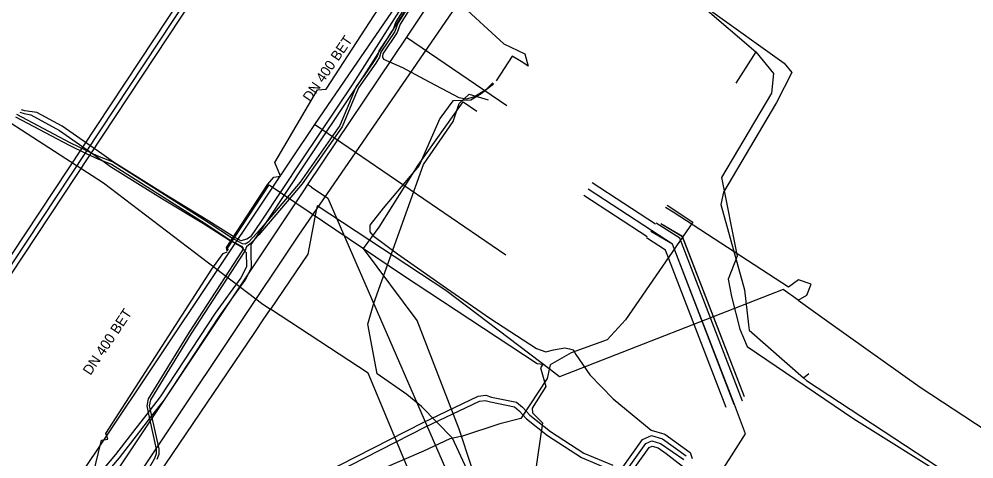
# Model space of a CAD drawing. Extents: x -598233 to -596890, y -1157848 to -1156431.
# Drawn here: x -597025.8 to -596950, y -1157211.3 to -1157176.4 of the extents above; entities that cross this region are included whole.
import ezdxf

# ---------------------------------------------------------------- set-up
doc = ezdxf.new("R2010")
doc.units = 0
for name, color, linetype in [('Vrstva 12', 7, 'Continuous'), ('Vrstva 13', 7, 'Continuous'), ('Vrstva 16', 7, 'Continuous'), ('Vrstva 19', 7, 'Continuous'), ('Vrstva 25', 7, 'Continuous'), ('Vrstva 26', 7, 'Continuous'), ('Vrstva 37', 7, 'Continuous'), ('Vrstva 38', 7, 'Continuous'), ('Vrstva 42', 7, 'Continuous'), ('Vrstva 55', 7, 'Continuous'), ('Vrstva 58', 7, 'Continuous'), ('Vrstva 9', 7, 'Continuous')]:
    doc.layers.add(name, color=color, linetype=linetype)

msp = doc.modelspace()

# ---------------------------------------------------------------- linework, layer by layer
at = {"layer": 'Vrstva 12'}
for points in [[(-597032.93, -1157180.49), (-597019.07, -1157189.44), (-597010.72, -1157195.79), (-597006.41, -1157199.06)], [(-596991.89, -1157197.98), (-597002.1, -1157191.27), (-597002.27, -1157192.15), (-597002.84, -1157195.09), (-597005.8, -1157199.46)], [(-596974.32, -1157191.21), (-596972.26, -1157192.55), (-596977.62, -1157200.29), (-596979.08, -1157201.89), (-596981.93, -1157202.92), (-596983.59, -1157203.86), (-596983.83, -1157204.96), (-596985.93, -1157208.12), (-596987.59, -1157208.54), (-596990.56, -1157209.52), (-596991.56, -1157209.75), (-596993.66, -1157210.73), (-596996.91, -1157212.12), (-596995.88, -1157213.75), (-596995.41, -1157214.6), (-596992.85, -1157218.63), (-596989.76, -1157224.28), (-596987.91, -1157228.68), (-596983.13, -1157231.73), (-596982.3, -1157232.26), (-596981.48, -1157232.92)], [(-596973.84, -1157191.76), (-596974.43, -1157191.38)], [(-596963.91, -1157198.75), (-596963.22, -1157198.34), (-596962.89, -1157197.48), (-596963.87, -1157197.14), (-596964.68, -1157197.72), (-596973.84, -1157191.76)], [(-596983.58, -1157204.27), (-596991.89, -1157197.98)], [(-596965.1, -1157197.9), (-596982.85, -1157204.83), (-596983.58, -1157204.27)], [(-596963.91, -1157198.75), (-596965.1, -1157197.9)], [(-596963.91, -1157198.75), (-596961.48, -1157200.48), (-596954.23, -1157205.63), (-596922.86, -1157226.22), (-596910.53, -1157233.01), (-596897.62, -1157241.15), (-596890.462, -1157245.858)], [(-597006.41, -1157199.06), (-597005.8, -1157199.46)], [(-597006.32, -1157200.23), (-597005.8, -1157199.46)], [(-596986.93, -1157231.06), (-596989.34, -1157225.4), (-596998.05, -1157204.54), (-597005.8, -1157199.46)], [(-597007.05, -1157201.3), (-597006.32, -1157200.23)], [(-597014.81, -1157212.79), (-597014.11, -1157211.71), (-597007.05, -1157201.3)]]:
    msp.add_lwpolyline(points, dxfattribs=at)
at = {"layer": 'Vrstva 13'}
for p, q in [((-596995.007, -1157177.869), (-596987.029, -1157183.302)), ((-597002.856, -1157189.564), (-597003.086, -1157189.907)), ((-597002.549, -1157189.771), (-597002.856, -1157189.564))]:
    msp.add_line(p, q, dxfattribs=at)
for points in [[(-596966.104, -1157134.786), (-596979.775, -1157155.164), (-596980.79, -1157156.59), (-596995.007, -1157177.869), (-597002.856, -1157189.564)], [(-597003.086, -1157189.907), (-597026.958, -1157225.685), (-597068.888, -1157237.453)], [(-597002.549, -1157189.771), (-597001.246, -1157190.659), (-596990.925, -1157214.348), (-596989.181, -1157218.344), (-596977.644, -1157244.817), (-596976.574, -1157247.274), (-596974.945, -1157251.212), (-596963.817, -1157276.638), (-596961.383, -1157282.176), (-596957.612, -1157290.782), (-596980.006, -1157323.339), (-596973.121, -1157340.272), (-596970.958, -1157345.591), (-596971.266, -1157347.162)]]:
    msp.add_lwpolyline(points, dxfattribs=at)
at = {"layer": 'Vrstva 16'}
for points in [[(-596998.41, -1157194.64), (-596997.18, -1157192.95), (-596994.09, -1157188.03), (-596990.51, -1157183.01), (-596989.41, -1157183.76)], [(-596961.79, -1157277.86), (-596964.67, -1157268.74), (-596973.69, -1157248.35), (-596975.09, -1157245.91), (-596978.64, -1157237.11), (-596983.01, -1157226.86), (-596984.86, -1157222.75), (-596987.47, -1157216.28), (-596989.85, -1157211.94), (-596990.83, -1157208.98), (-596994.15, -1157200.36), (-596998.41, -1157194.64)]]:
    msp.add_lwpolyline(points, dxfattribs=at)
at = {"layer": 'Vrstva 19'}
for points in [[(-596972.6, -1157147.95), (-596981.12, -1157160.92), (-597002.182, -1157191.556)], [(-597002.182, -1157191.556), (-597003.58, -1157193.59), (-597033.4, -1157238.15), (-597034.34, -1157239.12), (-597026.35, -1157257.65), (-597011.73, -1157291.16), (-597000.9, -1157316.42), (-597000.59, -1157317.13)]]:
    msp.add_lwpolyline(points, dxfattribs=at)
at = {"layer": 'Vrstva 25'}
msp.add_line((-597009.314, -1157170.114), (-597030.436, -1157202.016), dxfattribs=at)
at = {"layer": 'Vrstva 26'}
for p, q in [((-597030.551, -1157201.465), (-597009.427, -1157169.56)), ((-597009.202, -1157170.669), (-597030.103, -1157202.237))]:
    msp.add_line(p, q, dxfattribs=at)
at = {"layer": 'Vrstva 37'}
msp.add_line((-596975.561, -1157193.208), (-596980.59, -1157189.936), dxfattribs=at)
for points in [[(-596968.182, -1157206.411), (-596973.091, -1157193.703), (-596974.818, -1157192.69)], [(-596968.975, -1157207.006), (-596973.884, -1157194.298), (-596975.611, -1157193.285)], [(-596968.975, -1157207.006), (-596973.884, -1157194.298), (-596975.561, -1157193.208)], [(-596962.011, -1157224.901), (-596964.78, -1157223.133), (-596973.39, -1157217.635), (-596968.09, -1157209.335), (-596968.975, -1157207.006)]]:
    msp.add_lwpolyline(points, dxfattribs=at)
at = {"layer": 'Vrstva 38'}
for p, q in [((-596975.234, -1157192.705), (-596980.263, -1157189.433)), ((-596975.888, -1157193.711), (-596980.917, -1157190.439))]:
    msp.add_line(p, q, dxfattribs=at)
for points in [[(-596968.322, -1157206.754), (-596973.313, -1157193.835), (-596975.18, -1157192.621)], [(-596969.628, -1157207.258), (-596974.455, -1157194.761), (-596975.942, -1157193.795)]]:
    msp.add_lwpolyline(points, dxfattribs=at)
at = {"layer": 'Vrstva 42'}
for points in [[(-596993.928, -1157173.602), (-596995.861, -1157176.672), (-596996.094, -1157177.324), (-596996.1, -1157177.339), (-596996.164, -1157177.434), (-596997.205, -1157178.968), (-596997.265, -1157179.166), (-596997.319, -1157179.343), (-596997.614, -1157179.825), (-596998.375, -1157180.912), (-596998.998, -1157181.801), (-596999.097, -1157182.035), (-596999.532, -1157183.061), (-597000.298, -1157184.881), (-597003.449, -1157189.379), (-597006.068, -1157192.478), (-597006.874, -1157193.433), (-597007.561, -1157194.13), (-597007.803, -1157194.293), (-597008.013, -1157194.282), (-597008.909, -1157193.804), (-597010.665, -1157192.626), (-597018.335, -1157187.78), (-597019.381, -1157187.378), (-597019.912, -1157187.129), (-597020.337, -1157186.93), (-597021.695, -1157186.271), (-597025.953, -1157184.012)], [(-596993.76, -1157173.71), (-596995.68, -1157176.76), (-596995.92, -1157177.43), (-596997.04, -1157179.08), (-596997.151, -1157179.452), (-596997.446, -1157179.935), (-596998.822, -1157181.899), (-596999.348, -1157183.139), (-597000.122, -1157184.979), (-597003.291, -1157189.501), (-597006.726, -1157193.567), (-597007.028, -1157193.874), (-597007.419, -1157194.27), (-597007.706, -1157194.498), (-597007.844, -1157194.843), (-597007.856, -1157194.875), (-597012.096, -1157201.394), (-597015.335, -1157206.637), (-597015.428, -1157207.119), (-597015.356, -1157207.444), (-597015.243, -1157207.953), (-597014.67, -1157210.54), (-597014.68, -1157210.969), (-597014.829, -1157211.382)], [(-596994.499, -1157174.068), (-596999.276, -1157181.586), (-597003.32, -1157187.612), (-597006.546, -1157192.475), (-597007.402, -1157193.712), (-597007.689, -1157193.913), (-597008.155, -1157194.028), (-597008.849, -1157193.644), (-597010.921, -1157192.331), (-597014.153, -1157190.369), (-597018.269, -1157187.806), (-597019.202, -1157187.137), (-597022.349, -1157184.938), (-597024.347, -1157183.844), (-597025.293, -1157183.734), (-597025.582, -1157183.653)], [(-597019.913, -1157213.742), (-597017.796, -1157211.239), (-597016.165, -1157209.149), (-597015.402, -1157208.159), (-597015.243, -1157207.953), (-597014.227, -1157206.634), (-597009.862, -1157200.009), (-597007.803, -1157197.166), (-597007.298, -1157196.174), (-597007.339, -1157195.016), (-597007.349, -1157194.337), (-597007.028, -1157193.874), (-597006.214, -1157192.699), (-597006.068, -1157192.478), (-597002.988, -1157187.834), (-596999.097, -1157182.035), (-596998.942, -1157181.804), (-596998.375, -1157180.912), (-596997.265, -1157179.166), (-596996.164, -1157177.434), (-596996.094, -1157177.324), (-596994.161, -1157174.282)], [(-596993.592, -1157173.818), (-596995.499, -1157176.848), (-596995.74, -1157177.521), (-596996.875, -1157179.192), (-596996.897, -1157179.43), (-596996.82, -1157179.62), (-596995.33, -1157180.29), (-596993.59, -1157181.21), (-596990.85, -1157182.66), (-596990.24, -1157182.78), (-596989.66, -1157182.6), (-596988.66, -1157181.99), (-596988.15, -1157181.51)], [(-596990.792, -1157175.174), (-596987.283, -1157178.411), (-596985.616, -1157179.202), (-596985.335, -1157180.175), (-596985.767, -1157179.887), (-596986.026, -1157179.728), (-596986.608, -1157179.394), (-596987.895, -1157181.352)], [(-596988.093, -1157181.556), (-596988.216, -1157181.685), (-596989.073, -1157182.371), (-596989.898, -1157182.888), (-596991.326, -1157182.916), (-596992.371, -1157184.336), (-596993.997, -1157188.047), (-596996.87, -1157191.435), (-596997.904, -1157192.786), (-596997.927, -1157193.311), (-596997.685, -1157193.609), (-596995.722, -1157195.074), (-596991.832, -1157197.791), (-596988.383, -1157200.165), (-596984.689, -1157202.57), (-596983.938, -1157202.849), (-596983.329, -1157202.668), (-596982.443, -1157202.529), (-596982.075, -1157202.608), (-596981.766, -1157202.692), (-596981.572, -1157203.06), (-596980.445, -1157204.655), (-596978.601, -1157206.564), (-596975.591, -1157209.04), (-596974.492, -1157209.375), (-596972.484, -1157210.831), (-596972.314, -1157211.31)], [(-597026.047, -1157184.188), (-597021.785, -1157186.449), (-597020.423, -1157187.11), (-597019.459, -1157187.562), (-597019.105, -1157187.698), (-597018.425, -1157187.96), (-597010.775, -1157192.794), (-597009.011, -1157193.976), (-597008.107, -1157194.458), (-597008.004, -1157194.581), (-597008.011, -1157194.65), (-597008.024, -1157194.765), (-597012.264, -1157201.286), (-597015.525, -1157206.563), (-597015.632, -1157207.121), (-597015.515, -1157207.65), (-597015.402, -1157208.159), (-597014.87, -1157210.56), (-597014.88, -1157210.931), (-597015.011, -1157211.298), (-597015.516, -1157212.179)], [(-597025.698, -1157183.828), (-597025.347, -1157183.926), (-597024.836, -1157184.032), (-597022.561, -1157185.278), (-597019.912, -1157187.129), (-597019.434, -1157187.463), (-597019.105, -1157187.698), (-597018.491, -1157188.138), (-597014.363, -1157190.709), (-597011.131, -1157192.671), (-597009.053, -1157193.988), (-597008.153, -1157194.487), (-597008.011, -1157194.65), (-597007.844, -1157194.843), (-597007.742, -1157194.96), (-597007.702, -1157196.084), (-597008.145, -1157196.956), (-597010.192, -1157199.781), (-597014.553, -1157206.402), (-597015.356, -1157207.444), (-597015.515, -1157207.65), (-597016.481, -1157208.903), (-597018.106, -1157210.987), (-597020.221, -1157213.488)], [(-596968.18, -1157206.41), (-596973.09, -1157193.7), (-596974.82, -1157192.69)], [(-596968.98, -1157207.01), (-596973.88, -1157194.3), (-596975.61, -1157193.28)], [(-597005.552, -1157214.492), (-596993.683, -1157208.432), (-596989.314, -1157206.358), (-596988.713, -1157206.288), (-596988.244, -1157206.425), (-596986.26, -1157206.841), (-596985.787, -1157207.228), (-596985.215, -1157207.853), (-596983.57, -1157209.155), (-596980.928, -1157210.874), (-596978.625, -1157211.84)], [(-597005.364, -1157214.845), (-596993.506, -1157208.791), (-596989.202, -1157206.748), (-596988.747, -1157206.695), (-596988.341, -1157206.813), (-596986.438, -1157207.212), (-596986.063, -1157207.519), (-596985.488, -1157208.147), (-596983.804, -1157209.48), (-596981.116, -1157211.229), (-596978.797, -1157212.201)], [(-596977.97, -1157212.183), (-596976.265, -1157209.781), (-596975.564, -1157209.466), (-596974.673, -1157209.738), (-596972.801, -1157211.096)], [(-596977.711, -1157212.516), (-596976.002, -1157210.101), (-596975.537, -1157209.892), (-596974.849, -1157210.102), (-596972.992, -1157211.387)], [(-596977.003, -1157212.208), (-596975.738, -1157210.421), (-596975.509, -1157210.319), (-596975.025, -1157210.466), (-596974.38, -1157210.913), (-596972.38, -1157212.475)]]:
    msp.add_lwpolyline(points, dxfattribs=at)
at = {"layer": 'Vrstva 55'}
for points in [[(-597009.195, -1157194.841), (-597009.25, -1157194.82), (-597009.282, -1157194.558), (-597006.002, -1157189.543), (-597005.55, -1157188.98), (-597005.02, -1157188.91), (-597005.46, -1157187.82), (-597002.06, -1157182.05), (-597001.39, -1157182), (-596995.49, -1157172.9)], [(-597009.156, -1157194.776), (-597009.178, -1157194.582), (-597005.919, -1157189.598), (-596995.32, -1157196.73), (-596984.621, -1157203.752), (-596984.18, -1157203.82), (-596984.353, -1157204.097), (-596983.94, -1157205.59), (-596985.03, -1157207.3), (-596984.99, -1157207.69), (-596984.2, -1157208.46), (-596984.99, -1157213.92)], [(-597030.878, -1157239.493), (-597023.909, -1157236.564), (-597021.97, -1157235.8), (-597021.7, -1157235.49), (-597023.94, -1157229.29), (-597024.33, -1157229.14), (-597024.03, -1157228.89), (-597023.6, -1157226.75), (-597020.69, -1157221.03), (-597018.98, -1157218.19), (-597019.33, -1157217.4), (-597019.91, -1157212.67), (-597019.23, -1157209.85), (-597018.72, -1157209.76), (-597018.88, -1157209.32), (-597010.47, -1157196.29), (-597009.55, -1157195.05), (-597009.234, -1157194.909)]]:
    msp.add_lwpolyline(points, dxfattribs=at)
at = {"layer": 'Vrstva 58'}
for p, q in [((-596967.27, -1157179.04), (-596968.849, -1157181.519)), ((-596968.16, -1157197.91), (-596967.85, -1157200.7))]:
    msp.add_line(p, q, dxfattribs=at)
for points in [[(-596985.09, -1157158.25), (-596980.15, -1157161.97), (-596978.85, -1157164.76), (-596978.64, -1157166.74), (-596979.69, -1157170.6), (-596970.86, -1157175.76), (-596965.02, -1157179.94), (-596964.4, -1157180.68), (-596965.63, -1157183.07), (-596969.83, -1157190.18), (-596970.06, -1157191.15), (-596968.16, -1157197.91)], [(-596986.549, -1157168.374), (-596986.34, -1157168.71), (-596983.47, -1157170.59), (-596982.21, -1157170.57), (-596980.14, -1157170.67), (-596974.83, -1157174.01), (-596971.48, -1157175.44), (-596967.27, -1157179.04)], [(-596967.27, -1157179.04), (-596965.87, -1157180.75), (-596966.02, -1157182.32), (-596970, -1157189.01), (-596968.74, -1157195.25), (-596969.48, -1157197.07), (-596969.19, -1157198.45), (-596968.54, -1157201.04), (-596967.95, -1157202.42), (-596959.48, -1157208.15), (-596951.8, -1157212.96), (-596951.54, -1157213.85), (-596953.466, -1157216.467)], [(-596990.03, -1157212.54), (-596991.35, -1157209.68), (-596993.81, -1157207.18), (-596994.97, -1157206.22), (-596997.33, -1157204.59), (-596998.07, -1157200.65), (-596997.6, -1157198.98), (-596993.66, -1157187.98), (-596991.31, -1157184.57), (-596990.81, -1157183.14), (-596990.03, -1157182.41), (-596988.51, -1157182.84)], [(-596967.85, -1157200.7), (-596967.804, -1157201.11), (-596963.48, -1157204.9)], [(-596963.48, -1157204.9), (-596963.05, -1157204.55)], [(-596963.48, -1157204.9), (-596963.24, -1157205.11), (-596951.07, -1157213.1), (-596951.08, -1157213.42), (-596957.56, -1157223.4), (-596956.22, -1157229.85)]]:
    msp.add_lwpolyline(points, dxfattribs=at)
at = {"layer": 'Vrstva 9'}
msp.add_line((-596987.13, -1157195.17), (-597002.305, -1157184.795), dxfattribs=at)
for points in [[(-596985.831, -1157160.758), (-596999.263, -1157180.357), (-597002.305, -1157184.795)], [(-597002.305, -1157184.795), (-597005.903, -1157190.17), (-597019.228, -1157210.072), (-597021.976, -1157214.177), (-597026.974, -1157221.643)]]:
    msp.add_lwpolyline(points, dxfattribs=at)

# ---------------------------------------------------------------- texts
at = {"layer": 'Vrstva 12'}
for rotation, p in [(55.57691, (-597002.642, -1157183.068)), (56.20716, (-597020.096, -1157204.756))]:
    msp.add_text('DN 400 BET', height=0.8, rotation=rotation, dxfattribs=at).set_placement(p)

doc.saveas('drawing.dxf')
